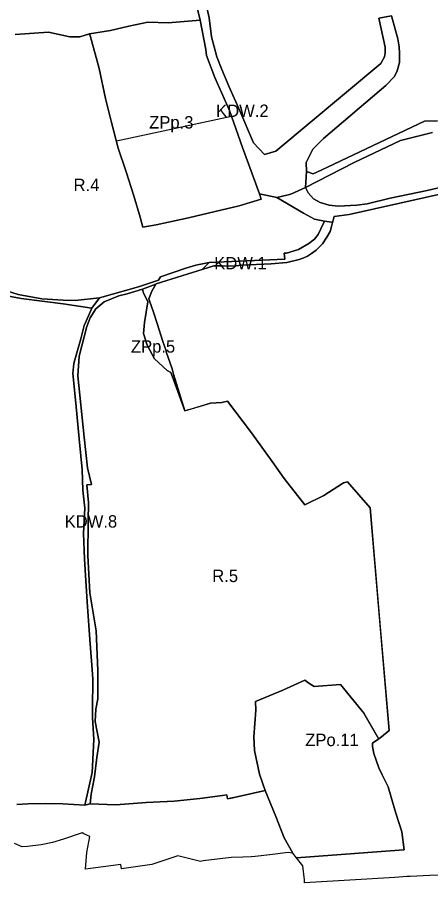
# Model space of a CAD drawing. Extents: x 7418114 to 7422197, y 5546299 to 5548348.
# Drawn here: x 7420446 to 7420780, y 5546328 to 5547025 of the extents above; entities that cross this region are included whole.
import ezdxf

# ---------------------------------------------------------------- set-up
doc = ezdxf.new("R2010")
doc.units = 0
for name, color, linetype in [('_ZWIERZYNIEC_KS_JOZEFA', 7, 'Continuous'), ('linie_lokalizacyjne', 7, 'Continuous'), ('linie_rozgraniczajace', 7, 'Continuous'), ('oznaczenia_przeznaczen', 7, 'Continuous')]:
    doc.layers.add(name, color=color, linetype=linetype)

msp = doc.modelspace()

# ---------------------------------------------------------------- linework, layer by layer
at = {"layer": '_ZWIERZYNIEC_KS_JOZEFA'}
for points in [[(7420795.96, 5546334.07), (7420779.04, 5546333.83), (7420763.12, 5546332.97), (7420760.55, 5546332.8), (7420750.81, 5546332.15), (7420714.42, 5546330.03), (7420678.04, 5546327.9), (7420677.85, 5546330.29), (7420676.53, 5546341.57), (7420671.55, 5546347.89), (7420754.39, 5546354.05), (7420758.34, 5546354.34), (7420756.33, 5546369.02), (7420751.91, 5546383.06), (7420750.82, 5546386.52), (7420745.38, 5546405.28), (7420740.59, 5546414.76), (7420737.97, 5546420.6), (7420733.96, 5546432.13), (7420732.83, 5546437.64), (7420732.67, 5546440.47), (7420737.74, 5546443.81), (7420740.09, 5546445.34), (7420746.12, 5546450.61), (7420746.14, 5546450.62), (7420730.8, 5546629.94), (7420712.61, 5546650.94), (7420709.34, 5546650.23), (7420708.49, 5546649.67), (7420693.62, 5546639.91), (7420678.1, 5546632.55), (7420661.55, 5546653.74), (7420651.8, 5546667.44), (7420635.03, 5546690.39), (7420615.72, 5546716.03), (7420611.12, 5546715.01), (7420602.11, 5546714.45), (7420587.24, 5546709.95), (7420581.44, 5546708.2), (7420579.25, 5546714.18), (7420572.27, 5546737.91), (7420571.07, 5546741.98), (7420566.46, 5546755.74), (7420566.2, 5546756.67), (7420563.75, 5546764.14), (7420559, 5546778.61), (7420556, 5546787.74), (7420553.01, 5546796.86), (7420552.47, 5546798.47), (7420554.86, 5546804.59), (7420558.12, 5546810.23), (7420558.31, 5546810.56), (7420604.91, 5546825.19), (7420611.78, 5546825.19), (7420620.57, 5546824.96), (7420627.07, 5546825.66), (7420651.12, 5546826.86), (7420663.78, 5546827.9), (7420673.74, 5546830.12), (7420677.37, 5546831.52), (7420680.45, 5546833.05), (7420683.43, 5546835.04), (7420687.31, 5546837.74), (7420692.47, 5546842.9), (7420696, 5546848.21), (7420698.62, 5546852.79), (7420701.8, 5546864.9), (7420713.93, 5546866.43), (7420836.51, 5546894.02)], [(7420446, 5546390.94), (7420454.82, 5546391.43), (7420469.1, 5546391.65), (7420483.03, 5546391.48), (7420500.62, 5546390.49), (7420505.02, 5546391.6), (7420525.77, 5546390.58), (7420550.24, 5546392.46), (7420572.87, 5546393.73), (7420593.62, 5546395.68), (7420611.88, 5546398.31), (7420615.39, 5546398.67), (7420615.71, 5546395.47), (7420620.21, 5546396.38), (7420624.72, 5546397.29), (7420633.25, 5546399.2), (7420646.22, 5546402.11), (7420654.75, 5546381.24), (7420661.5, 5546364.01), (7420668.47, 5546351.79), (7420664.78, 5546352.24), (7420649.83, 5546350.42), (7420638.16, 5546349.01), (7420634.88, 5546348.61), (7420628.27, 5546348.53), (7420618.7, 5546348.32), (7420596.3, 5546345.43), (7420594.06, 5546345.06), (7420575.85, 5546349.64), (7420554.74, 5546342.68), (7420530.28, 5546339.2), (7420529.89, 5546342.68), (7420501.36, 5546338.9), (7420502.43, 5546352.32), (7420504.69, 5546365.26), (7420499.99, 5546367.38), (7420498.5, 5546368.05), (7420483.56, 5546362.99), (7420474.66, 5546360.36), (7420465.56, 5546358.51), (7420454.38, 5546357.08), (7420450.08, 5546356.93), (7420444.11, 5546359.52)]]:
    msp.add_lwpolyline(points, dxfattribs=at)
at = {"layer": 'linie_lokalizacyjne'}
msp.add_lwpolyline([(7420619.16, 5546945.38), (7420526.2, 5546925.72)], dxfattribs=at)
at = {"layer": 'linie_rozgraniczajace'}
for points in [[(7420587.9, 5547048.16), (7420593.71, 5547023.13), (7420567.82, 5547021.06), (7420551.55, 5547021.48), (7420536.25, 5547018.35), (7420521.42, 5547014.74), (7420504.62, 5547012.05), (7420496.78, 5547009.62), (7420488.59, 5547009.59), (7420471.43, 5547013.51), (7420444.45, 5547011.59)], [(7420596.12, 5547046.74), (7420600.89, 5547025.01), (7420602.89, 5547009.66), (7420607.07, 5546993.58), (7420611.26, 5546983.35), (7420616.93, 5546969.99), (7420625.62, 5546950.14), (7420636.88, 5546924.36), (7420645.67, 5546914.91), (7420654.67, 5546917.6), (7420739.37, 5546988.15), (7420742.43, 5546993.56), (7420743.05, 5546996.82), (7420742.95, 5547001.52), (7420737.94, 5547024.77), (7420748.01, 5547026.59), (7420753.27, 5547008.15), (7420754.27, 5547001.68), (7420754.65, 5546996.47), (7420754.55, 5546989), (7420752.7, 5546982.36), (7420750.56, 5546977.83), (7420743.39, 5546970.48), (7420693.19, 5546927.73), (7420684.65, 5546919.08), (7420679.26, 5546908.35), (7420679.43, 5546901.08), (7420678.82, 5546888.24), (7420675.69, 5546886.8), (7420667.01, 5546882.9), (7420663.54, 5546881.96), (7420655.67, 5546880.34), (7420641.5, 5546883.1), (7420627.92, 5546920.59), (7420617.42, 5546950.29), (7420605.61, 5546976.89), (7420598.84, 5546994.68), (7420598.23, 5546999.56), (7420593.71, 5547023.13), (7420587.9, 5547048.16)], [(7420785.11, 5546942.04), (7420774.73, 5546941.68), (7420691.25, 5546902.31), (7420684.89, 5546899.35), (7420679.43, 5546901.08), (7420679.26, 5546908.35), (7420684.65, 5546919.08), (7420693.19, 5546927.73), (7420743.39, 5546970.48), (7420750.56, 5546977.83), (7420752.7, 5546982.36), (7420754.55, 5546989), (7420754.65, 5546996.47), (7420754.27, 5547001.68), (7420753.27, 5547008.15), (7420748.01, 5547026.59), (7420737.94, 5547024.77), (7420742.95, 5547001.52), (7420743.05, 5546996.82), (7420742.43, 5546993.56), (7420739.37, 5546988.15), (7420654.67, 5546917.6), (7420645.67, 5546914.91), (7420636.88, 5546924.36), (7420625.62, 5546950.14), (7420616.93, 5546969.99), (7420611.26, 5546983.35), (7420607.07, 5546993.58), (7420602.89, 5547009.66), (7420600.89, 5547025.01), (7420596.12, 5547046.74)], [(7420444.45, 5547011.59), (7420471.43, 5547013.51), (7420488.59, 5547009.59), (7420496.78, 5547009.62), (7420504.62, 5547012.05), (7420505.28, 5547009.64), (7420512.17, 5546984.31), (7420517.27, 5546960.04), (7420521.84, 5546941.7), (7420527.74, 5546920.11), (7420533.96, 5546900.88), (7420540.15, 5546881.6), (7420545.42, 5546864.24), (7420547.48, 5546856.25), (7420558.38, 5546858.25), (7420584.38, 5546863.93), (7420605.77, 5546868.92), (7420625.31, 5546873.52), (7420642.97, 5546879), (7420641.5, 5546883.1), (7420655.67, 5546880.34), (7420677.15, 5546867.56), (7420686.03, 5546862.87), (7420694.03, 5546861.09), (7420691.18, 5546854.9), (7420688.86, 5546850.52), (7420685.94, 5546846.64), (7420681.29, 5546843.25), (7420673.1, 5546838.29), (7420663.3, 5546835.37), (7420661.42, 5546835.31), (7420662.04, 5546830.53), (7420601.13, 5546827.78), (7420590.36, 5546825.76), (7420582.27, 5546823.31), (7420561.7, 5546816.39), (7420560.03, 5546813.58), (7420544, 5546808.33), (7420512.63, 5546799.24), (7420492.89, 5546797.13), (7420483.2, 5546797.49), (7420465.92, 5546798.64), (7420446.86, 5546802.13), (7420436.66, 5546805.15)], [(7420781.14, 5546932.55), (7420755.47, 5546926.13), (7420717.92, 5546908.34), (7420678.82, 5546888.24), (7420679.43, 5546901.08), (7420684.89, 5546899.35), (7420691.25, 5546902.31), (7420774.73, 5546941.68), (7420785.11, 5546942.04)], [(7420846.65, 5546902.19), (7420776.89, 5546885.89), (7420746.98, 5546879.57), (7420728.35, 5546875.16), (7420720, 5546874.1), (7420705.01, 5546873.18), (7420697.78, 5546874.07), (7420690.61, 5546876.14), (7420685.09, 5546879.08), (7420680.78, 5546883.88), (7420678.82, 5546888.24), (7420717.92, 5546908.34), (7420755.47, 5546926.13), (7420781.14, 5546932.55)], [(7420922.27, 5546898.98), (7420924.92, 5546904.72), (7420922.7, 5546912.64), (7420836.51, 5546894.02), (7420713.93, 5546866.43), (7420701.8, 5546864.9), (7420700.53, 5546860.07), (7420699.77, 5546860.32), (7420694.03, 5546861.09), (7420686.03, 5546862.87), (7420677.15, 5546867.56), (7420655.67, 5546880.34)], [(7420655.67, 5546880.34), (7420663.54, 5546881.96), (7420667.01, 5546882.9), (7420675.69, 5546886.8), (7420678.82, 5546888.24), (7420680.78, 5546883.88), (7420685.09, 5546879.08), (7420690.61, 5546876.14), (7420697.78, 5546874.07), (7420705.01, 5546873.18), (7420720, 5546874.1), (7420728.35, 5546875.16), (7420746.98, 5546879.57), (7420776.89, 5546885.89), (7420846.65, 5546902.19)], [(7420595.41, 5546822.21), (7420601.13, 5546827.78), (7420662.04, 5546830.53), (7420661.42, 5546835.31), (7420663.3, 5546835.37), (7420673.1, 5546838.29), (7420681.29, 5546843.25), (7420685.94, 5546846.64), (7420688.86, 5546850.52), (7420691.18, 5546854.9), (7420694.03, 5546861.09), (7420699.77, 5546860.32), (7420700.53, 5546860.07)], [(7420700.53, 5546860.07), (7420698.62, 5546852.79), (7420696, 5546848.21), (7420692.47, 5546842.9), (7420687.31, 5546837.74), (7420683.43, 5546835.04), (7420680.45, 5546833.05), (7420677.37, 5546831.52), (7420673.74, 5546830.12), (7420663.78, 5546827.9), (7420651.12, 5546826.86), (7420627.07, 5546825.66), (7420620.57, 5546824.96), (7420611.78, 5546825.19), (7420604.91, 5546825.19), (7420595.41, 5546822.21)], [(7420595.41, 5546822.21), (7420558.31, 5546810.56), (7420558.12, 5546810.23), (7420547.32, 5546806.38), (7420534.98, 5546802.44), (7420528.19, 5546800.92), (7420516.39, 5546796.22), (7420509.51, 5546790.52), (7420505.15, 5546783.29), (7420502.47, 5546776.18), (7420496.13, 5546752.31), (7420494.99, 5546736.42), (7420500.3, 5546687.15), (7420502.84, 5546662.29), (7420506.05, 5546648.98), (7420502.27, 5546648.63), (7420503.79, 5546634.28), (7420503.43, 5546619.15), (7420503.17, 5546591.57), (7420504.66, 5546561.66), (7420509.81, 5546531.05), (7420511.18, 5546498.95), (7420511.28, 5546476.02), (7420509.49, 5546467.86), (7420509.17, 5546457.86), (7420512.28, 5546441.2), (7420510.45, 5546428.83), (7420508.56, 5546413.17), (7420505.85, 5546399.14), (7420505.02, 5546391.6), (7420505.02, 5546391.6), (7420500.62, 5546390.49), (7420506.52, 5546416.69), (7420508.01, 5546443.21), (7420506.89, 5546461.15), (7420506.87, 5546468.18), (7420507.06, 5546491.84), (7420506.74, 5546499.64), (7420505.08, 5546520.31), (7420502.8, 5546550.21), (7420501.47, 5546571.3), (7420500.41, 5546588.97), (7420499.53, 5546609.36), (7420500.65, 5546629.91), (7420499.09, 5546644.3), (7420498.65, 5546660.97), (7420496.16, 5546685.59), (7420493.54, 5546714.48), (7420491.02, 5546738.35), (7420491.86, 5546746.5), (7420492.69, 5546749.28), (7420497.45, 5546766.19), (7420498.89, 5546771.62), (7420500.24, 5546776.99), (7420501.68, 5546780.55), (7420506.24, 5546790.95), (7420512.63, 5546799.24), (7420544, 5546808.33), (7420560.03, 5546813.58), (7420561.7, 5546816.39), (7420582.27, 5546823.31), (7420590.36, 5546825.76), (7420601.13, 5546827.78), (7420595.41, 5546822.21)], [(7420436.66, 5546805.15), (7420446.86, 5546802.13), (7420465.92, 5546798.64), (7420483.2, 5546797.49), (7420492.89, 5546797.13), (7420512.63, 5546799.24), (7420506.24, 5546790.95), (7420483.29, 5546794.55), (7420449.38, 5546798.75), (7420426.19, 5546803.13)], [(7420426.19, 5546803.13), (7420449.38, 5546798.75), (7420483.29, 5546794.55), (7420506.24, 5546790.95), (7420501.68, 5546780.55), (7420500.24, 5546776.99), (7420498.89, 5546771.62), (7420497.45, 5546766.19), (7420492.69, 5546749.28), (7420491.86, 5546746.5), (7420491.02, 5546738.35), (7420493.54, 5546714.48), (7420496.16, 5546685.59), (7420498.65, 5546660.97), (7420499.09, 5546644.3), (7420500.65, 5546629.91), (7420499.53, 5546609.36), (7420500.41, 5546588.97), (7420501.47, 5546571.3), (7420502.8, 5546550.21), (7420505.08, 5546520.31), (7420506.74, 5546499.64), (7420507.06, 5546491.84), (7420506.87, 5546468.18), (7420506.89, 5546461.15), (7420508.01, 5546443.21), (7420506.52, 5546416.69), (7420500.62, 5546390.49), (7420483.03, 5546391.48), (7420469.1, 5546391.65), (7420454.82, 5546391.43), (7420446, 5546390.94)], [(7420737.74, 5546443.81), (7420726.17, 5546464.17), (7420706.85, 5546487.6), (7420685.79, 5546486.15), (7420681.45, 5546488.72), (7420678.23, 5546491.27), (7420660.37, 5546483), (7420638.45, 5546473.97), (7420638.54, 5546466.87), (7420637.1, 5546445.58), (7420637.7, 5546434.55), (7420641.54, 5546415.51), (7420646.22, 5546402.11), (7420624.72, 5546397.29), (7420615.71, 5546395.47), (7420615.39, 5546398.67), (7420611.88, 5546398.31), (7420593.62, 5546395.68), (7420572.87, 5546393.73), (7420550.24, 5546392.46), (7420525.77, 5546390.58), (7420505.02, 5546391.6), (7420505.85, 5546399.14), (7420508.56, 5546413.17), (7420510.45, 5546428.83), (7420512.28, 5546441.2), (7420509.17, 5546457.86), (7420509.49, 5546467.86), (7420511.28, 5546476.02), (7420511.18, 5546498.95), (7420509.81, 5546531.05), (7420504.66, 5546561.66), (7420503.17, 5546591.57), (7420503.43, 5546619.15), (7420503.79, 5546634.28), (7420502.27, 5546648.63), (7420506.05, 5546648.98), (7420502.84, 5546662.29), (7420500.3, 5546687.15), (7420494.99, 5546736.42), (7420496.13, 5546752.31), (7420502.47, 5546776.18), (7420505.15, 5546783.29), (7420509.51, 5546790.52), (7420516.39, 5546796.22), (7420528.19, 5546800.92), (7420534.98, 5546802.44), (7420547.32, 5546806.38), (7420548.17, 5546803.06), (7420549.38, 5546800.71), (7420551.52, 5546796.03), (7420548.75, 5546779.36), (7420548.18, 5546770.63), (7420551.03, 5546761.31), (7420556.93, 5546750.05), (7420567.27, 5546740.8), (7420570.16, 5546739.11), (7420571.38, 5546735.62), (7420581.44, 5546708.2), (7420602.11, 5546714.45), (7420611.12, 5546715.01), (7420615.72, 5546716.03), (7420635.03, 5546690.39), (7420651.8, 5546667.44), (7420661.55, 5546653.74), (7420678.1, 5546632.55), (7420693.62, 5546639.91), (7420708.49, 5546649.67), (7420709.34, 5546650.23), (7420712.61, 5546650.94), (7420730.8, 5546629.94), (7420738.47, 5546540.28), (7420746.12, 5546450.61), (7420740.09, 5546445.34), (7420737.74, 5546443.81)], [(7420737.74, 5546443.81), (7420732.67, 5546440.47), (7420732.83, 5546437.64), (7420733.96, 5546432.13), (7420737.97, 5546420.6), (7420740.59, 5546414.76), (7420745.38, 5546405.28), (7420750.82, 5546386.52), (7420751.91, 5546383.06), (7420756.33, 5546369.02), (7420758.34, 5546354.34), (7420754.39, 5546354.05), (7420671.55, 5546347.89), (7420668.47, 5546351.79), (7420661.5, 5546364.01), (7420654.75, 5546381.24), (7420646.22, 5546402.11), (7420641.54, 5546415.51), (7420637.7, 5546434.55), (7420637.1, 5546445.58), (7420638.54, 5546466.87), (7420638.45, 5546473.97), (7420660.37, 5546483), (7420678.23, 5546491.27), (7420681.45, 5546488.72), (7420685.79, 5546486.15), (7420706.85, 5546487.6), (7420726.17, 5546464.17)]]:
    msp.add_lwpolyline(points, dxfattribs=at)
for points in [[(7420504.62, 5547012.05), (7420521.42, 5547014.74), (7420536.25, 5547018.35), (7420551.55, 5547021.48), (7420567.82, 5547021.06), (7420593.71, 5547023.13), (7420598.23, 5546999.56), (7420598.84, 5546994.68), (7420605.61, 5546976.89), (7420617.42, 5546950.29), (7420627.92, 5546920.59), (7420641.5, 5546883.1), (7420642.97, 5546879), (7420625.31, 5546873.52), (7420605.77, 5546868.92), (7420584.38, 5546863.93), (7420558.38, 5546858.25), (7420547.48, 5546856.25), (7420545.42, 5546864.24), (7420540.15, 5546881.6), (7420533.96, 5546900.88), (7420527.74, 5546920.11), (7420521.84, 5546941.7), (7420517.27, 5546960.04), (7420512.17, 5546984.31), (7420505.28, 5547009.64)], [(7420548.18, 5546770.63), (7420548.75, 5546779.36), (7420551.52, 5546796.03), (7420549.38, 5546800.71), (7420548.17, 5546803.06), (7420547.32, 5546806.38), (7420558.12, 5546810.23), (7420554.86, 5546804.59), (7420552.47, 5546798.47), (7420553.01, 5546796.86), (7420556, 5546787.74), (7420559, 5546778.61), (7420563.75, 5546764.14), (7420566.2, 5546756.67), (7420566.46, 5546755.74), (7420571.07, 5546741.98), (7420572.27, 5546737.91), (7420581.44, 5546708.2), (7420571.38, 5546735.62), (7420570.16, 5546739.11), (7420567.27, 5546740.8), (7420556.93, 5546750.05), (7420551.03, 5546761.31)]]:
    msp.add_lwpolyline(points, close=True, dxfattribs=at)

# ---------------------------------------------------------------- texts
at = {"layer": 'oznaczenia_przeznaczen'}
for s, p in [('KDW.2', (7420606.63, 5546945.13)), ('ZPp.3', (7420552.64, 5546935.82)), ('R.4', (7420491.65, 5546885.34)), ('KDW.1', (7420605.11, 5546822.33)), ('ZPp.5', (7420537.93, 5546755.17)), ('KDW.8', (7420484.45, 5546614.15)), ('R.5', (7420603.51, 5546570.23)), ('ZPo.11', (7420678.52, 5546438))]:
    msp.add_text(s, height=10, dxfattribs=at).set_placement(p)

doc.saveas('drawing.dxf')
